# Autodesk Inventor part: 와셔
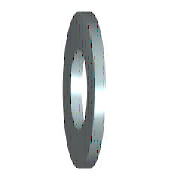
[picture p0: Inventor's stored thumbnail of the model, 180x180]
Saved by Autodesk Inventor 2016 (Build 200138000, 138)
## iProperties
Created: 2012-02
Part Number: 와셔
Material: 강철, 연강
Description: 평면 와셔
Document SubType Name: Modeling
Standard: KS B 1326
Designer: mduedu
Standards Organization: KS
Language: ko-KR
Size Designation: 8x15.5
Categories: <MemberInstance><Categories><Category DisplayName="조임쇠" InternalName="e4da775c-781d-43d5-af7c-5136215cf5a6" Mnemonic="FSTN"><Category DisplayName="와셔" InternalN
Density: 1 g/cm^3
Appearance: 파란색 - 벽 페인트 - 광택
IsCustomPart: 1
Author: mduedu
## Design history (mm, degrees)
sketch "스케치"
  geometry: C1 r 7.75 at (0, 0); C2 r 4.2 at (0, 0); 1 further point
  constraints: 2 centre point, 2 coincident
  dimensions: "d0" = 8.4 diameter of C2 (= SD1); "d1" = 15.5 diameter of C1 (= SD2)
extrude "본체" new body sketch "스케치" distance "d2" = 1.6 (= SD); taper "d3" = 0 deg
workaxis "Work Axis1"
workplane "Work Plane1"
body "Solid1"
other parameters: "SD1" = 8.4 [user parameter; used in 1 equation term], "SD2" = 15.5 [user parameter; used in 1 equation term], "SD" = 1.6 [user parameter; used in 1 equation term], "d4" = 0, "d5" = 0, "d6" = 0, "d7" = 0, "NND" = 8 [user parameter]
